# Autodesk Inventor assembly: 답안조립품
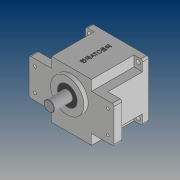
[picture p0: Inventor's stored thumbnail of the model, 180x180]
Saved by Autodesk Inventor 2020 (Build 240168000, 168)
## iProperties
Created: 2020-07
Part Number: 답안조립품
Document SubType Name: Assembly
Designer: PC312-
Author: PC312-
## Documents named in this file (10)
- C:\Users\PC312-\Desktop\700718V1001\답안조립품.iam
- C:\Users\PC312-\Desktop\700718V1001\01.본체.ipt
- C:\Users\PC312-\Desktop\700718V1001\오일 실 17 32 8.ipt
- C:\Users\PC312-\Desktop\700718V1001\베어링 6003.ipt
- C:\Users\PC312-\Desktop\700718V1001\베어링 608.ipt
- C:\Users\PC312-\Desktop\700718V1001\커버.ipt
- C:\Users\PC312-\Desktop\700718V1001\오일 실 8 22 7.ipt
- C:\Users\PC312-\Desktop\700718V1001\서브 축.ipt
- C:\Users\PC312-\Desktop\700718V1001\메인 축.ipt
- C:\Users\PC312-\Desktop\700718V1001\볼트 M4.ipt
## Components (1 placed, 1 different names)
1. 01.본체:1
